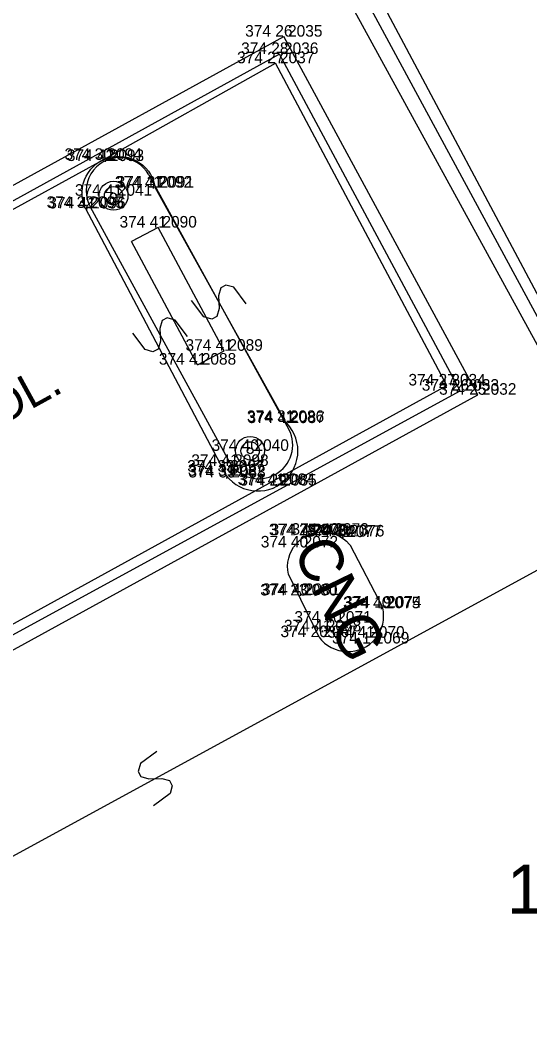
# Model space of a CAD drawing. Extents: x -601196 to -600262, y -1082523 to -1081922.
# Drawn here: x -600526.73 to -600517.93, y -1082160.04 to -1082142.44 of the extents above; entities that cross this region are included whole.
import ezdxf

# ---------------------------------------------------------------- set-up
doc = ezdxf.new("R2010")
doc.units = 0
for name, color, linetype in [('Vrstva 1', 7, 'Continuous'), ('Vrstva 10', 7, 'Continuous'), ('Vrstva 11', 7, 'Continuous'), ('Vrstva 2', 7, 'Continuous'), ('Vrstva 20', 7, 'Continuous'), ('Vrstva 25', 7, 'Continuous'), ('Vrstva 3', 7, 'Continuous'), ('Vrstva 40', 7, 'Continuous'), ('Vrstva 41', 7, 'Continuous'), ('Vrstva 47', 7, 'Continuous')]:
    doc.layers.add(name, color=color, linetype=linetype)

msp = doc.modelspace()

# ---------------------------------------------------------------- linework, layer by layer
at = {"layer": 'Vrstva 1'}
for p, q in [((-600522.18, -1082142.72), (-600522.18, -1082142.72)), ((-600522.25, -1082143.02), (-600522.25, -1082143.02)), ((-600522.32, -1082143.18), (-600522.32, -1082143.18)), ((-600525.3, -1082144.85), (-600525.3, -1082144.85)), ((-600525.26, -1082144.87), (-600525.26, -1082144.87)), ((-600524.43, -1082145.33), (-600524.43, -1082145.33)), ((-600524.4, -1082145.33), (-600524.4, -1082145.33)), ((-600525.12, -1082145.47), (-600525.12, -1082145.47)), ((-600525.61, -1082145.68), (-600525.61, -1082145.68)), ((-600525.58, -1082145.69), (-600525.58, -1082145.69)), ((-600524.35, -1082146.02), (-600524.35, -1082146.02)), ((-600523.21, -1082148.15), (-600523.21, -1082148.15)), ((-600523.67, -1082148.39), (-600523.67, -1082148.39)), ((-600519.36, -1082148.75), (-600519.36, -1082148.75)), ((-600519.13, -1082148.84), (-600519.13, -1082148.84)), ((-600518.83, -1082148.91), (-600518.83, -1082148.91)), ((-600522.15, -1082149.38), (-600522.15, -1082149.38)), ((-600522.14, -1082149.4), (-600522.14, -1082149.4)), ((-600522.76, -1082149.88), (-600522.76, -1082149.88)), ((-600523.18, -1082150.24), (-600523.18, -1082150.24)), ((-600523.11, -1082150.14), (-600523.11, -1082150.14)), ((-600523.17, -1082150.31), (-600523.17, -1082150.31)), ((-600523.16, -1082150.34), (-600523.16, -1082150.34)), ((-600522.31, -1082150.47), (-600522.31, -1082150.47)), ((-600522.28, -1082150.48), (-600522.28, -1082150.48)), ((-600521.77, -1082151.34), (-600521.77, -1082151.34)), ((-600521.74, -1082151.34), (-600521.74, -1082151.34)), ((-600521.38, -1082151.33), (-600521.38, -1082151.33)), ((-600521.11, -1082151.36), (-600521.11, -1082151.36)), ((-600521.16, -1082151.37), (-600521.16, -1082151.37)), ((-600521.91, -1082151.55), (-600521.91, -1082151.55)), ((-600521.92, -1082152.38), (-600521.92, -1082152.38)), ((-600521.89, -1082152.37), (-600521.89, -1082152.37)), ((-600520.47, -1082152.59), (-600520.47, -1082152.59)), ((-600520.49, -1082152.6), (-600520.49, -1082152.6)), ((-600521.33, -1082152.85), (-600521.33, -1082152.85)), ((-600521.57, -1082153.1), (-600521.57, -1082153.1)), ((-600521.51, -1082153), (-600521.51, -1082153)), ((-600520.76, -1082153.11), (-600520.76, -1082153.11)), ((-600520.68, -1082153.21), (-600520.68, -1082153.21))]:
    msp.add_line(p, q, dxfattribs=at)
at = {"layer": 'Vrstva 10'}
for p, q in [((-600515.15, -1082152.48), (-600521.24, -1082141.18)), ((-600522.15, -1082149.38), (-600524.4, -1082145.33)), ((-600525.61, -1082145.68), (-600523.17, -1082150.31)), ((-600520.47, -1082152.59), (-600521.029, -1082151.517)), ((-600521.57, -1082153.1), (-600522.099, -1082152.011))]:
    msp.add_line(p, q, dxfattribs=at)
for points in [[(-600525.61, -1082145.68), (-600525.635, -1082145.613), (-600525.652, -1082145.544), (-600525.662, -1082145.474), (-600525.663, -1082145.402), (-600525.657, -1082145.331), (-600525.643, -1082145.262), (-600525.621, -1082145.194), (-600525.591, -1082145.129), (-600525.554, -1082145.068), (-600525.511, -1082145.011), (-600525.462, -1082144.96), (-600525.407, -1082144.914), (-600525.348, -1082144.875), (-600525.284, -1082144.843), (-600525.217, -1082144.818), (-600525.148, -1082144.8), (-600525.077, -1082144.791), (-600525.006, -1082144.789), (-600524.935, -1082144.796), (-600524.865, -1082144.81), (-600524.798, -1082144.832), (-600524.733, -1082144.862), (-600524.672, -1082144.899), (-600524.615, -1082144.942), (-600524.564, -1082144.991), (-600524.518, -1082145.046), (-600524.479, -1082145.105), (-600524.447, -1082145.169), (-600524.422, -1082145.236), (-600524.404, -1082145.305), (-600524.4, -1082145.33)], [(-600523.17, -1082150.31), (-600523.121, -1082150.366), (-600523.066, -1082150.416), (-600523.006, -1082150.46), (-600522.942, -1082150.497), (-600522.874, -1082150.528), (-600522.803, -1082150.55), (-600522.73, -1082150.566), (-600522.656, -1082150.573), (-600522.582, -1082150.572), (-600522.508, -1082150.563), (-600522.436, -1082150.546), (-600522.365, -1082150.522), (-600522.298, -1082150.49), (-600522.235, -1082150.451), (-600522.176, -1082150.406), (-600522.122, -1082150.355), (-600522.074, -1082150.298), (-600522.033, -1082150.236), (-600521.998, -1082150.17), (-600521.971, -1082150.101), (-600521.951, -1082150.029), (-600521.939, -1082149.956), (-600521.935, -1082149.882), (-600521.939, -1082149.807), (-600521.951, -1082149.734), (-600521.97, -1082149.662), (-600521.998, -1082149.593), (-600522.032, -1082149.527), (-600522.074, -1082149.466), (-600522.122, -1082149.409), (-600522.15, -1082149.38)], [(-600522.099, -1082152.011), (-600522.11, -1082151.943), (-600522.112, -1082151.873), (-600522.107, -1082151.804), (-600522.094, -1082151.736), (-600522.073, -1082151.669), (-600522.044, -1082151.606), (-600522.009, -1082151.546), (-600521.967, -1082151.491), (-600521.918, -1082151.441), (-600521.865, -1082151.397), (-600521.806, -1082151.359), (-600521.744, -1082151.328), (-600521.678, -1082151.305), (-600521.611, -1082151.289), (-600521.542, -1082151.281), (-600521.472, -1082151.281), (-600521.403, -1082151.289), (-600521.336, -1082151.305), (-600521.27, -1082151.329), (-600521.208, -1082151.36), (-600521.15, -1082151.398), (-600521.096, -1082151.442), (-600521.048, -1082151.492), (-600521.029, -1082151.517)], [(-600521.57, -1082153.1), (-600521.525, -1082153.154), (-600521.474, -1082153.203), (-600521.418, -1082153.245), (-600521.358, -1082153.281), (-600521.294, -1082153.31), (-600521.227, -1082153.331), (-600521.158, -1082153.345), (-600521.088, -1082153.35), (-600521.018, -1082153.348), (-600520.948, -1082153.338), (-600520.88, -1082153.32), (-600520.815, -1082153.294), (-600520.752, -1082153.261), (-600520.694, -1082153.222), (-600520.641, -1082153.175), (-600520.594, -1082153.124), (-600520.552, -1082153.067), (-600520.518, -1082153.006), (-600520.49, -1082152.941), (-600520.47, -1082152.874), (-600520.458, -1082152.804), (-600520.454, -1082152.734), (-600520.457, -1082152.664), (-600520.469, -1082152.595), (-600520.47, -1082152.59)]]:
    msp.add_lwpolyline(points, dxfattribs=at)
at = {"layer": 'Vrstva 11'}
for p, q in [((-600537.38, -1082151.07), (-600522.18, -1082142.72)), ((-600518.83, -1082148.91), (-600522.18, -1082142.72)), ((-600522.25, -1082143.02), (-600537.06, -1082151.19)), ((-600519.13, -1082148.84), (-600522.25, -1082143.02)), ((-600525.3, -1082144.85), (-600522.32, -1082143.18)), ((-600519.36, -1082148.75), (-600522.32, -1082143.18)), ((-600532.79, -1082148.95), (-600525.3, -1082144.85)), ((-600524.35, -1082146.02), (-600524.81, -1082146.26)), ((-600523.21, -1082148.15), (-600524.35, -1082146.02)), ((-600523.67, -1082148.39), (-600524.81, -1082146.26)), ((-600523.67, -1082148.39), (-600523.21, -1082148.15)), ((-600533.97, -1082156.94), (-600519.13, -1082148.84)), ((-600533.9, -1082156.74), (-600519.36, -1082148.75)), ((-600528.95, -1082154.47), (-600518.83, -1082148.91))]:
    msp.add_line(p, q, dxfattribs=at)
at = {"layer": 'Vrstva 20'}
for p, q in [((-600525.27, -1082144.87), (-600525.25, -1082144.87)), ((-600525.26, -1082144.855), (-600525.26, -1082144.87)), ((-600525.26, -1082144.885), (-600525.26, -1082144.87)), ((-600524.44, -1082145.33), (-600524.42, -1082145.33)), ((-600524.43, -1082145.315), (-600524.43, -1082145.33)), ((-600524.43, -1082145.345), (-600524.43, -1082145.33)), ((-600525.59, -1082145.69), (-600525.57, -1082145.69)), ((-600525.58, -1082145.675), (-600525.58, -1082145.69)), ((-600525.58, -1082145.705), (-600525.58, -1082145.69)), ((-600522.15, -1082149.4), (-600522.13, -1082149.4)), ((-600522.14, -1082149.385), (-600522.14, -1082149.4)), ((-600522.14, -1082149.415), (-600522.14, -1082149.4)), ((-600523.11, -1082150.125), (-600523.11, -1082150.14)), ((-600523.12, -1082150.14), (-600523.1, -1082150.14)), ((-600523.11, -1082150.155), (-600523.11, -1082150.14)), ((-600523.17, -1082150.34), (-600523.15, -1082150.34)), ((-600523.16, -1082150.325), (-600523.16, -1082150.34)), ((-600523.16, -1082150.355), (-600523.16, -1082150.34)), ((-600522.32, -1082150.47), (-600522.3, -1082150.47)), ((-600522.31, -1082150.455), (-600522.31, -1082150.47)), ((-600522.31, -1082150.485), (-600522.31, -1082150.47)), ((-600521.75, -1082151.34), (-600521.73, -1082151.34)), ((-600521.74, -1082151.325), (-600521.74, -1082151.34)), ((-600521.74, -1082151.355), (-600521.74, -1082151.34)), ((-600521.16, -1082151.355), (-600521.16, -1082151.37)), ((-600521.17, -1082151.37), (-600521.15, -1082151.37)), ((-600521.16, -1082151.385), (-600521.16, -1082151.37)), ((-600521.9, -1082152.37), (-600521.88, -1082152.37)), ((-600521.89, -1082152.355), (-600521.89, -1082152.37)), ((-600521.89, -1082152.385), (-600521.89, -1082152.37)), ((-600520.49, -1082152.585), (-600520.49, -1082152.6)), ((-600520.5, -1082152.6), (-600520.48, -1082152.6)), ((-600520.49, -1082152.615), (-600520.49, -1082152.6)), ((-600521.52, -1082153), (-600521.5, -1082153)), ((-600521.51, -1082152.985), (-600521.51, -1082153)), ((-600521.51, -1082153.015), (-600521.51, -1082153)), ((-600520.77, -1082153.11), (-600520.75, -1082153.11)), ((-600520.76, -1082153.095), (-600520.76, -1082153.11)), ((-600520.76, -1082153.125), (-600520.76, -1082153.11))]:
    msp.add_line(p, q, dxfattribs=at)
at = {"layer": 'Vrstva 25'}
for centre, radius in [((-600525.12, -1082145.47), 0.25), ((-600525.12, -1082145.47), 0.158), ((-600525.12, -1082145.47), 0.05), ((-600522.76, -1082149.88), 0.25), ((-600522.76, -1082149.88), 0.158), ((-600522.76, -1082149.88), 0.05)]:
    msp.add_circle(centre, radius, dxfattribs=at)
at = {"layer": 'Vrstva 47'}
for p, q in [((-600522.29, -1082138.73), (-600514.93, -1082152.58)), ((-600516.16, -1082151.05), (-600522.62, -1082139.23)), ((-600524.51, -1082145.11), (-600522.09, -1082149.51)), ((-600523.11, -1082150.08), (-600525.52, -1082145.67)), ((-600523.264, -1082147.062), (-600523.304, -1082147.198)), ((-600523.177, -1082147.014), (-600523.264, -1082147.062)), ((-600523.041, -1082147.053), (-600523.177, -1082147.014)), ((-600522.829, -1082147.336), (-600523.041, -1082147.053)), ((-600523.558, -1082147.566), (-600523.77, -1082147.283)), ((-600523.304, -1082147.198), (-600523.295, -1082147.421)), ((-600523.295, -1082147.421), (-600523.335, -1082147.557)), ((-600524.279, -1082147.627), (-600524.319, -1082147.763)), ((-600524.191, -1082147.579), (-600524.279, -1082147.627)), ((-600524.055, -1082147.619), (-600524.191, -1082147.579)), ((-600523.844, -1082147.902), (-600524.055, -1082147.619)), ((-600523.422, -1082147.605), (-600523.558, -1082147.566)), ((-600523.335, -1082147.557), (-600523.422, -1082147.605)), ((-600524.319, -1082147.763), (-600524.31, -1082147.986)), ((-600524.574, -1082148.13), (-600524.785, -1082147.847)), ((-600524.31, -1082147.986), (-600524.35, -1082148.122)), ((-600524.438, -1082148.17), (-600524.574, -1082148.13)), ((-600524.35, -1082148.122), (-600524.438, -1082148.17)), ((-600532.64, -1082160.04), (-600516.16, -1082151.05)), ((-600524.372, -1082155.074), (-600524.655, -1082155.285)), ((-600524.655, -1082155.285), (-600524.695, -1082155.421)), ((-600524.695, -1082155.421), (-600524.647, -1082155.509)), ((-600524.647, -1082155.509), (-600524.511, -1082155.549)), ((-600524.511, -1082155.549), (-600524.288, -1082155.541)), ((-600524.288, -1082155.541), (-600524.152, -1082155.58)), ((-600524.152, -1082155.58), (-600524.104, -1082155.668)), ((-600524.104, -1082155.668), (-600524.144, -1082155.804)), ((-600524.144, -1082155.804), (-600524.427, -1082156.015))]:
    msp.add_line(p, q, dxfattribs=at)
for centre, radius, start, end in [((-600525.016, -1082145.388), 0.577, 28.783, 209.2298), ((-600522.61, -1082149.777), 0.585, 211.2217, 27.1732)]:
    msp.add_arc(centre, radius, start, end, dxfattribs=at)

# ---------------------------------------------------------------- texts
at = {"layer": 'Vrstva 2'}
for s, p in [(' 2035', (-600522.18, -1082142.72)), (' 2036', (-600522.25, -1082143.02)), (' 2037', (-600522.32, -1082143.18)), (' 2094', (-600525.3, -1082144.85)), (' 2093', (-600525.26, -1082144.87)), (' 2092', (-600524.43, -1082145.33)), (' 2091', (-600524.4, -1082145.33)), (' 2041', (-600525.12, -1082145.47)), (' 2095', (-600525.61, -1082145.68)), (' 2096', (-600525.58, -1082145.69)), (' 2090', (-600524.35, -1082146.02)), (' 2089', (-600523.21, -1082148.15)), (' 2088', (-600523.67, -1082148.39)), (' 2034', (-600519.36, -1082148.75)), (' 2033', (-600519.13, -1082148.84)), (' 2032', (-600518.83, -1082148.91)), (' 2086', (-600522.15, -1082149.38)), (' 2087', (-600522.14, -1082149.4)), (' 2040', (-600522.76, -1082149.88)), (' 2098', (-600523.11, -1082150.14)), (' 2097', (-600523.18, -1082150.24)), (' 2082', (-600523.17, -1082150.31)), (' 2083', (-600523.16, -1082150.34)), (' 2084', (-600522.31, -1082150.47)), (' 2085', (-600522.28, -1082150.48)), (' 2078', (-600521.77, -1082151.34)), (' 2079', (-600521.74, -1082151.34)), (' 2073', (-600521.38, -1082151.33)), (' 2077', (-600521.16, -1082151.37)), (' 2076', (-600521.11, -1082151.36)), (' 2072', (-600521.91, -1082151.55)), (' 2080', (-600521.92, -1082152.38)), (' 2081', (-600521.89, -1082152.37)), (' 2075', (-600520.49, -1082152.6)), (' 2074', (-600520.47, -1082152.59)), (' 2071', (-600521.33, -1082152.85)), (' 2067', (-600521.57, -1082153.1)), (' 2068', (-600521.51, -1082153)), (' 2070', (-600520.76, -1082153.11)), (' 2069', (-600520.68, -1082153.21))]:
    msp.add_text(s, height=0.2, dxfattribs=at).set_placement(p)
at = {"layer": 'Vrstva 3'}
for s, p in [('374 26 ', (-600522.846, -1082142.72)), ('374 28 ', (-600522.916, -1082143.02)), ('374 27 ', (-600522.986, -1082143.18)), ('374 30 ', (-600525.966, -1082144.85)), ('374 42 ', (-600525.926, -1082144.87)), ('374 41 ', (-600525.096, -1082145.33)), ('374 31 ', (-600525.066, -1082145.33)), ('374 41 ', (-600525.786, -1082145.47)), ('374 32 ', (-600526.276, -1082145.68)), ('374 41 ', (-600526.246, -1082145.69)), ('374 41 ', (-600525.016, -1082146.02)), ('374 41 ', (-600523.876, -1082148.15)), ('374 41 ', (-600524.336, -1082148.39)), ('374 27 ', (-600520.026, -1082148.75)), ('374 26 ', (-600519.796, -1082148.84)), ('374 25 ', (-600519.496, -1082148.91)), ('374 31 ', (-600522.816, -1082149.38)), ('374 41 ', (-600522.806, -1082149.4)), ('374 40 ', (-600523.426, -1082149.88)), ('374 41 ', (-600523.776, -1082150.14)), ('374 33 ', (-600523.846, -1082150.24)), ('374 31 ', (-600523.836, -1082150.31)), ('374 39 ', (-600523.826, -1082150.34)), ('374 41 ', (-600522.976, -1082150.47)), ('374 29 ', (-600522.946, -1082150.48)), ('374 25 ', (-600522.436, -1082151.34)), ('374 41 ', (-600522.406, -1082151.34)), ('374 40 ', (-600522.046, -1082151.33)), ('374 41 ', (-600521.826, -1082151.37)), ('374 24 ', (-600521.776, -1082151.36)), ('374 40 ', (-600522.576, -1082151.55)), ('374 23 ', (-600522.586, -1082152.38)), ('374 40 ', (-600522.556, -1082152.37)), ('374 40 ', (-600521.156, -1082152.6)), ('374 19 ', (-600521.136, -1082152.59)), ('374 40 ', (-600521.996, -1082152.85)), ('374 20 ', (-600522.236, -1082153.1)), ('374 41 ', (-600522.176, -1082153)), ('374 41 ', (-600521.426, -1082153.11)), ('374 17 ', (-600521.346, -1082153.21))]:
    msp.add_text(s, height=0.2, dxfattribs=at).set_placement(p)
at = {"layer": 'Vrstva 40'}
msp.add_text('ZÁMK.DL.', height=0.6, rotation=28.7896, dxfattribs=at).set_placement((-600529.208, -1082150.632))
at = {"layer": 'Vrstva 41'}
msp.add_text('CNG', height=0.75, rotation=295.9249, dxfattribs=at).set_placement((-600522.032, -1082151.593))
at = {"layer": 'Vrstva 47'}
msp.add_text('1525/9', height=0.85, dxfattribs=at).set_placement((-600518.326, -1082157.88))

doc.saveas('drawing.dxf')
